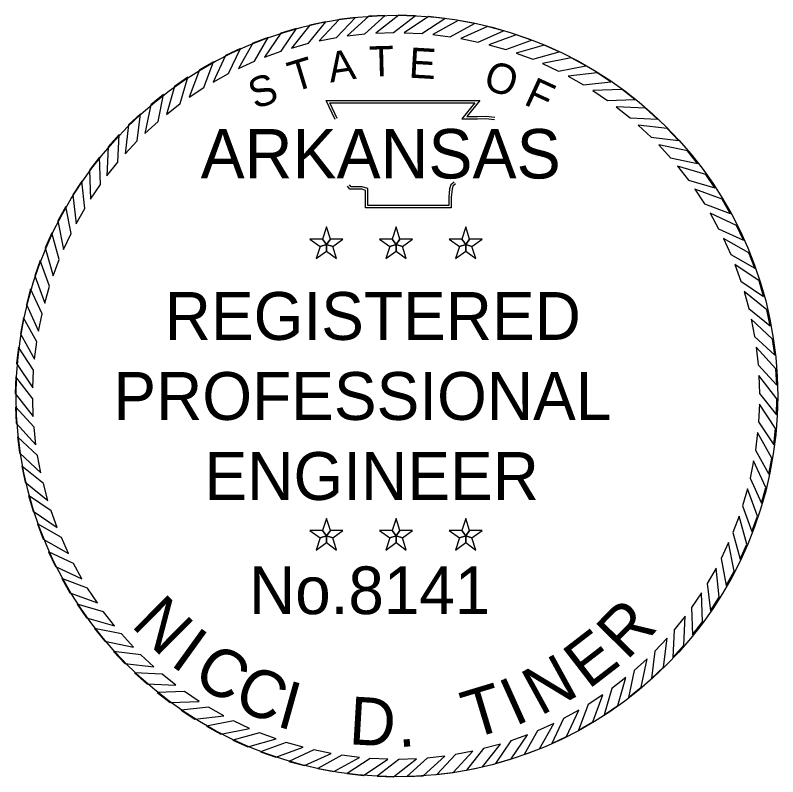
# Model space of a CAD drawing. Extents: x 0 to 19, y -0.6 to 11.2.
# Drawn here: x 17.822 to 19.023, y 9.084 to 10.284 of the extents above; entities that cross this region are included whole.
import ezdxf

# ---------------------------------------------------------------- set-up
doc = ezdxf.new("R2010")
doc.units = 0
for name, color, linetype in [('G-ANNO-STMP', 7, 'Continuous'), ('G-No Plot-Stamp-1', 7, 'Continuous'), ('G-No Plot-Stamp-2', 7, 'Continuous')]:
    doc.layers.add(name, color=color, linetype=linetype)

msp = doc.modelspace()

# ---------------------------------------------------------------- linework, layer by layer
at = {"layer": 'G-ANNO-STMP'}
for points in [[(18.3112, 10.2732), (18.2859, 10.2679), (18.2573, 10.2319), (18.2842, 10.2393)], [(18.3578, 10.2801), (18.3322, 10.2768), (18.3008, 10.2431), (18.3282, 10.2484)], [(18.4048, 10.2833), (18.379, 10.282), (18.3451, 10.2509), (18.3728, 10.254)], [(18.4519, 10.2828), (18.4261, 10.2835), (18.3899, 10.2552), (18.4177, 10.2561)], [(18.4988, 10.2786), (18.4732, 10.2813), (18.4348, 10.256), (18.4627, 10.2546)], [(18.5453, 10.2707), (18.5199, 10.2755), (18.4797, 10.2532), (18.5073, 10.2497)], [(18.2652, 10.2627), (18.2405, 10.2554), (18.2148, 10.2173), (18.241, 10.2268)], [(18.591, 10.2592), (18.5661, 10.266), (18.5242, 10.2469), (18.5515, 10.2412)], [(18.2203, 10.2486), (18.1962, 10.2394), (18.1735, 10.1994), (18.1989, 10.2109)], [(18.6356, 10.2442), (18.6113, 10.2529), (18.5681, 10.2371), (18.5949, 10.2294)], [(18.6789, 10.2257), (18.6554, 10.2362), (18.6111, 10.224), (18.6372, 10.2141)], [(18.1766, 10.2311), (18.1533, 10.22), (18.1338, 10.1783), (18.1582, 10.1918)], [(18.7207, 10.2039), (18.698, 10.2162), (18.6529, 10.2074), (18.6781, 10.1956)], [(18.1344, 10.2101), (18.112, 10.1973), (18.0959, 10.1542), (18.1192, 10.1695)], [(18.7606, 10.1788), (18.739, 10.1929), (18.6933, 10.1877), (18.7175, 10.1739)], [(18.0939, 10.1859), (18.0726, 10.1714), (18.06, 10.1272), (18.082, 10.1443)], [(18.7984, 10.1507), (18.778, 10.1665), (18.732, 10.1649), (18.7551, 10.1492)], [(18.0555, 10.1587), (18.0354, 10.1425), (18.0263, 10.0974), (18.0469, 10.1162)], [(18.0194, 10.1284), (18.0006, 10.1107), (17.995, 10.0651), (18.0141, 10.0854)], [(18.8339, 10.1197), (18.8148, 10.137), (18.7688, 10.1391), (18.7906, 10.1216)], [(18.8669, 10.0861), (18.8491, 10.1048), (18.8035, 10.1104), (18.8238, 10.0914)], [(17.9857, 10.0955), (17.9684, 10.0764), (17.9664, 10.0304), (17.9838, 10.0522)], [(18.8971, 10.0499), (18.8809, 10.07), (18.8358, 10.0792), (18.8546, 10.0586)], [(17.9547, 10.06), (17.939, 10.0396), (17.9406, 9.9936), (17.9562, 10.0167)], [(18.9244, 10.0115), (18.9098, 10.0328), (18.8656, 10.0455), (18.8827, 10.0235)], [(17.9266, 10.0222), (17.9125, 10.0006), (17.9177, 9.9549), (17.9315, 9.9791)], [(18.9485, 9.9711), (18.9357, 9.9935), (18.8926, 10.0096), (18.9079, 9.9863)], [(17.9016, 9.9823), (17.8892, 9.9596), (17.898, 9.9145), (17.9099, 9.9397)], [(18.9695, 9.9289), (18.9584, 9.9522), (18.9167, 9.9716), (18.9302, 9.9472)], [(18.3122, 9.9224), (18.3184, 9.9309), (18.3122, 9.9499), (18.3061, 9.9309)], [(18.4219, 9.9224), (18.4281, 9.9309), (18.4219, 9.9499), (18.4158, 9.9309)], [(18.5317, 9.9224), (18.5378, 9.9309), (18.5317, 9.9499), (18.5255, 9.9309)], [(17.8798, 9.9405), (17.8692, 9.917), (17.8815, 9.8727), (17.8913, 9.8987)], [(18.3122, 9.9224), (18.3061, 9.9309), (18.2861, 9.9309), (18.3023, 9.9192)], [(18.3122, 9.9224), (18.3222, 9.9192), (18.3383, 9.9309), (18.3184, 9.9309)], [(18.4219, 9.9224), (18.4158, 9.9309), (18.3958, 9.9309), (18.412, 9.9192)], [(18.4219, 9.9224), (18.4319, 9.9192), (18.448, 9.9309), (18.4281, 9.9309)], [(18.5317, 9.9224), (18.5255, 9.9309), (18.5056, 9.9309), (18.5217, 9.9192)], [(18.5317, 9.9224), (18.5416, 9.9192), (18.5577, 9.9309), (18.5378, 9.9309)], [(18.987, 9.8852), (18.9779, 9.9093), (18.9378, 9.9319), (18.9493, 9.9065)], [(18.3122, 9.9224), (18.3023, 9.9192), (18.2961, 9.9003), (18.3122, 9.912)], [(18.3122, 9.9224), (18.3122, 9.912), (18.3283, 9.9003), (18.3222, 9.9192)], [(18.4219, 9.9224), (18.412, 9.9192), (18.4058, 9.9003), (18.4219, 9.912)], [(18.4219, 9.9224), (18.4219, 9.912), (18.4381, 9.9003), (18.4319, 9.9192)], [(18.5317, 9.9224), (18.5217, 9.9192), (18.5155, 9.9003), (18.5317, 9.912)], [(18.5317, 9.9224), (18.5317, 9.912), (18.5478, 9.9003), (18.5416, 9.9192)], [(17.8613, 9.8972), (17.8526, 9.8729), (17.8683, 9.8297), (17.8761, 9.8564)], [(19.0011, 9.8402), (18.9939, 9.865), (18.9557, 9.8907), (18.9652, 9.8645)], [(17.8462, 9.8525), (17.8395, 9.8276), (17.8586, 9.7858), (17.8642, 9.8131)], [(19.0116, 9.7943), (19.0063, 9.8195), (18.9703, 9.8482), (18.9777, 9.8213)], [(17.8347, 9.8069), (17.83, 9.7815), (17.8523, 9.7413), (17.8558, 9.7689)], [(19.0185, 9.7477), (19.0152, 9.7733), (18.9816, 9.8046), (18.9868, 9.7772)], [(17.8269, 9.7604), (17.8241, 9.7347), (17.8495, 9.6964), (17.8508, 9.7242)], [(19.0217, 9.7007), (19.0204, 9.7264), (18.9893, 9.7603), (18.9924, 9.7326)], [(17.8227, 9.7135), (17.8219, 9.6877), (17.8503, 9.6514), (17.8494, 9.6793)], [(19.0212, 9.6536), (19.0219, 9.6793), (18.9936, 9.7156), (18.9945, 9.6877)], [(17.8222, 9.6664), (17.8235, 9.6406), (17.8545, 9.6067), (17.8515, 9.6344)], [(19.017, 9.6066), (19.0198, 9.6323), (18.9944, 9.6706), (18.9931, 9.6428)], [(19.0091, 9.5602), (19.0139, 9.5855), (18.9916, 9.6258), (18.9881, 9.5981)], [(17.8254, 9.6194), (17.8287, 9.5938), (17.8623, 9.5624), (17.8571, 9.5898)], [(18.9976, 9.5145), (19.0044, 9.5394), (18.9853, 9.5812), (18.9797, 9.5539)], [(17.8322, 9.5728), (17.8375, 9.5475), (17.8735, 9.5189), (17.8662, 9.5458)], [(18.9826, 9.4698), (18.9913, 9.4941), (18.9755, 9.5374), (18.9678, 9.5106)], [(17.8427, 9.5268), (17.85, 9.5021), (17.8881, 9.4764), (17.8787, 9.5026)], [(18.9641, 9.4265), (18.9747, 9.4501), (18.9624, 9.4944), (18.9525, 9.4683)], [(17.8568, 9.4819), (17.866, 9.4578), (17.906, 9.4351), (17.8946, 9.4605)], [(18.3122, 9.463), (18.3184, 9.4715), (18.3122, 9.4904), (18.3061, 9.4715)], [(18.4219, 9.463), (18.4281, 9.4715), (18.4219, 9.4904), (18.4158, 9.4715)], [(18.5317, 9.463), (18.5378, 9.4715), (18.5317, 9.4904), (18.5255, 9.4715)], [(18.3122, 9.463), (18.3061, 9.4715), (18.2861, 9.4715), (18.3023, 9.4598)], [(18.3122, 9.463), (18.3222, 9.4598), (18.3383, 9.4715), (18.3184, 9.4715)], [(18.4219, 9.463), (18.4158, 9.4715), (18.3958, 9.4715), (18.412, 9.4598)], [(18.4219, 9.463), (18.4319, 9.4598), (18.448, 9.4715), (18.4281, 9.4715)], [(18.5317, 9.463), (18.5255, 9.4715), (18.5056, 9.4715), (18.5217, 9.4598)], [(18.5317, 9.463), (18.5416, 9.4598), (18.5577, 9.4715), (18.5378, 9.4715)], [(18.3122, 9.463), (18.3023, 9.4598), (18.2961, 9.4408), (18.3122, 9.4525)], [(18.3122, 9.463), (18.3122, 9.4525), (18.3283, 9.4408), (18.3222, 9.4598)], [(18.4219, 9.463), (18.412, 9.4598), (18.4058, 9.4408), (18.4219, 9.4525)], [(18.4219, 9.463), (18.4219, 9.4525), (18.4381, 9.4408), (18.4319, 9.4598)], [(18.5317, 9.463), (18.5217, 9.4598), (18.5155, 9.4408), (18.5317, 9.4525)], [(18.5317, 9.463), (18.5317, 9.4525), (18.5478, 9.4408), (18.5416, 9.4598)], [(18.9423, 9.3848), (18.9546, 9.4074), (18.9459, 9.4526), (18.934, 9.4273)], [(17.8744, 9.4382), (17.8854, 9.4148), (17.9271, 9.3954), (17.9137, 9.4198)], [(18.9172, 9.3449), (18.9313, 9.3665), (18.9261, 9.4122), (18.9123, 9.3879)], [(17.8953, 9.3959), (17.9082, 9.3736), (17.9513, 9.3575), (17.9359, 9.3808)], [(18.8891, 9.307), (18.9049, 9.3275), (18.9033, 9.3734), (18.8876, 9.3504)], [(17.9195, 9.3555), (17.9341, 9.3342), (17.9783, 9.3215), (17.9612, 9.3436)], [(18.8582, 9.2715), (18.8755, 9.2907), (18.8775, 9.3366), (18.8601, 9.3149)], [(17.9468, 9.3171), (17.963, 9.297), (18.0081, 9.2879), (17.9893, 9.3085)], [(18.8245, 9.2386), (18.8432, 9.2563), (18.8489, 9.302), (18.8298, 9.2816)], [(17.977, 9.281), (17.9947, 9.2622), (18.0404, 9.2566), (18.02, 9.2757)], [(18.7883, 9.2084), (18.8084, 9.2246), (18.8176, 9.2696), (18.797, 9.2509)], [(18.01, 9.2473), (18.0291, 9.23), (18.075, 9.228), (18.0533, 9.2454)], [(18.7499, 9.1811), (18.7712, 9.1957), (18.7839, 9.2399), (18.7619, 9.2228)], [(18.0455, 9.2163), (18.0659, 9.2006), (18.1119, 9.2022), (18.0888, 9.2178)], [(18.7095, 9.1569), (18.7319, 9.1698), (18.748, 9.2128), (18.7247, 9.1975)], [(18.0833, 9.1882), (18.1049, 9.1741), (18.1506, 9.1793), (18.1264, 9.1931)], [(18.6673, 9.136), (18.6906, 9.147), (18.71, 9.1887), (18.6856, 9.1753)], [(18.1232, 9.1632), (18.1458, 9.1508), (18.191, 9.1596), (18.1657, 9.1714)], [(18.6236, 9.1184), (18.6477, 9.1276), (18.6703, 9.1676), (18.6449, 9.1561)], [(18.1649, 9.1413), (18.1885, 9.1308), (18.2328, 9.1431), (18.2067, 9.1529)], [(18.5786, 9.1043), (18.6034, 9.1116), (18.6291, 9.1497), (18.6029, 9.1403)], [(18.2083, 9.1228), (18.2326, 9.1142), (18.2758, 9.1299), (18.249, 9.1377)], [(18.5327, 9.0938), (18.5579, 9.0991), (18.5866, 9.1351), (18.5597, 9.1278)], [(18.2529, 9.1078), (18.2778, 9.1011), (18.3197, 9.1201), (18.2924, 9.1258)], [(18.4861, 9.0869), (18.5117, 9.0903), (18.543, 9.1239), (18.5157, 9.1187)], [(18.2986, 9.0963), (18.324, 9.0916), (18.3642, 9.1139), (18.3365, 9.1173)], [(18.345, 9.0885), (18.3707, 9.0857), (18.4091, 9.1111), (18.3812, 9.1124)], [(18.392, 9.0843), (18.4178, 9.0835), (18.454, 9.1118), (18.4261, 9.1109)], [(18.4391, 9.0837), (18.4649, 9.085), (18.4988, 9.1161), (18.4711, 9.113)]]:
    msp.add_lwpolyline(points, close=True, dxfattribs=at)
for points in [[(18.3258, 10.119), (18.3118, 10.1493), (18.5538, 10.1494), (18.5336, 10.124), (18.5501, 10.1242), (18.5638, 10.1244), (18.5775, 10.1229)], [(18.3293, 10.1206), (18.3178, 10.1455), (18.5459, 10.1456), (18.5256, 10.1201), (18.5501, 10.1204), (18.5636, 10.1206), (18.5771, 10.1191)], [(18.5133, 10.0205), (18.5082, 10.0164), (18.5064, 10.0099), (18.505, 9.9969), (18.505, 9.9838), (18.3776, 9.9838), (18.3776, 10.0025), (18.3776, 10.0104), (18.3688, 10.013), (18.3511, 10.013), (18.3488, 10.0165)], [(18.5157, 10.0176), (18.5116, 10.0142), (18.5102, 10.0092), (18.5088, 9.9966), (18.5088, 9.9799), (18.3737, 9.9799), (18.3737, 10.0025), (18.3737, 10.0075), (18.3683, 10.0092), (18.349, 10.0092), (18.3456, 10.0144)]]:
    msp.add_lwpolyline(points, dxfattribs=at)
at = {"layer": 'G-No Plot-Stamp-1'}
msp.add_circle((18.4233, 9.6835), 0.6, dxfattribs=at)
at = {"layer": 'G-No Plot-Stamp-2'}
msp.add_circle((18.4233, 9.6835), 0.6, dxfattribs=at)

# ---------------------------------------------------------------- texts
at = {"layer": 'G-ANNO-STMP'}
for s, height, rotation, p in [('A', 0.0477, 8.6788, (18.3184, 10.1773)), ('T', 0.0477, 1.4789, (18.3801, 10.1868)), ('E', 0.0477, 356.672, (18.4412, 10.1853)), ('T', 0.0477, 16.9015, (18.2605, 10.1621)), ('O', 0.0477, 341.2218, (18.5571, 10.1689)), ('S', 0.0477, 19.7726, (18.1998, 10.1349)), ('F', 0.0477, 335.3628, (18.6214, 10.1438)), ('N', 0.0754, 315.2676, (18.0028, 9.3216)), ('R', 0.0754, 45.478, (18.7853, 9.2657)), ('I', 0.0754, 324.2141, (18.0641, 9.2609)), ('E', 0.0754, 37.6498, (18.725, 9.2201)), ('C', 0.0754, 328.6873, (18.0982, 9.2342)), ('N', 0.0754, 28.7033, (18.6493, 9.1786)), ('C', 0.0754, 336.5155, (18.1624, 9.1943)), ('I', 0.0754, 24.2301, (18.6092, 9.1624)), ('I', 0.0754, 344.3437, (18.2314, 9.1635)), ('T', 0.0754, 16.7747, (18.54, 9.1425)), ('D', 0.0754, 356.6451, (18.3466, 9.1349)), ('.', 0.0754, 4.846, (18.4256, 9.1298))]:
    msp.add_text(s, height=height, rotation=rotation, dxfattribs=at).set_placement(p)
for s, height, p in [('ARKANSAS', 0.07791, (18.114, 10.0263)), ('REGISTERED', 0.07543, (18.0574, 9.7719)), ('PROFESSIONAL', 0.07543, (17.9765, 9.6458)), ('ENGINEER', 0.07543, (18.1202, 9.5197)), ('No.8141', 0.07513, (18.1905, 9.3398))]:
    msp.add_text(s, height=height, dxfattribs=at).set_placement(p)

doc.saveas('drawing.dxf')
